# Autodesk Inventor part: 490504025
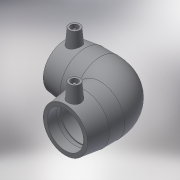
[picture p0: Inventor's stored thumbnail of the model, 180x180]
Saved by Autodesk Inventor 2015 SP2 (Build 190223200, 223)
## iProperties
Created: 2017-06
Part Number: 490504025
Material: Generic
Description: PLASSON 90° ELBOW 25
Document SubType Name: Modeling
Designer: KIM
Mass: 55.0731 g
Surface Area: 148.067 cm^2
Volume: 55.0731 cm^3
Density: 1 g/cm^3
Appearance: Default
Author: KIM
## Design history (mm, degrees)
derived "490504.ipt"
feature "Solid1::490504.ipt"
tag "TaggingFeature1"
body "Solid1"
other parameters: "d2" = 36, "d4" = 19.41176, "d5" = 32.4, "d8" = 168 deg, "d10" = 14.8, "d11" = 4.93333, "d14" = 17.6296, "d18" = 25, "d19" = 3.52592, "d20" = 168 deg, "d22" = 33.12, "d23" = 36, "d24" = 32.1264, "d29" = 38, "d30" = 15, "d31" = 39.6, "d34" = 5 deg, "d35" = 15, "d39" = 5 deg, "d41" = 4, "d42" = 14, "d43" = 0, "d45" = 4, "d46" = 14, "d47" = 0, "d49" = 25, "d50" = 21.25, "d51" = 14.8, "d52" = 37, "d54" = 90 deg, "d65" = 25, "d67" = 45 deg, "d71" = 90 deg, "d75" = 1.8, "d82" = 45 deg, "d83" = 37, "d84" = 32.4, "d86" = 16.2, "d87" = 90 deg, "d90" = 37, "d91" = 0, "d92" = 37, "d93" = 0, "d94" = 90 deg, "d95" = 16.56, "d98" = 66, "d101" = 3, "d102" = 0, "d103" = 3, "d104" = 0, "d105" = 10.73, "d106" = 2.6825, "d107" = 66, "d110" = 20.35, "d_" = 25, "L_" = 66, "L_1" = 37, "D_" = 36, "A_" = 38, "d_2" = 12
